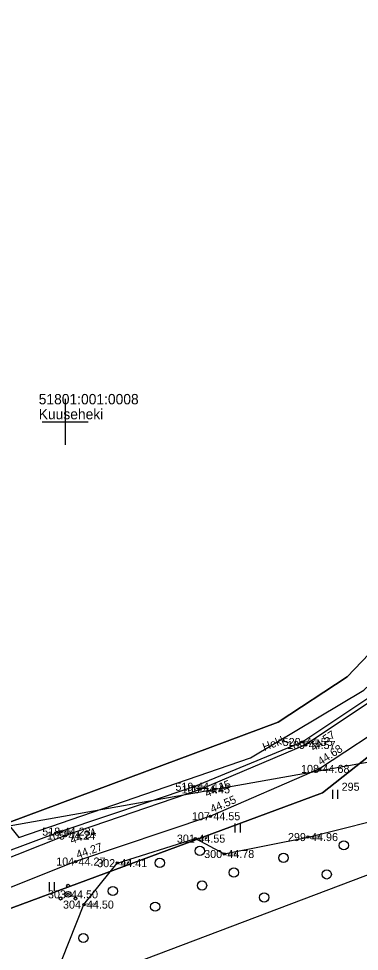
# Model space of a CAD drawing. Extents: x 505800 to 507326, y 6540058 to 6542128.
# Drawn here: x 506246 to 506275.6, y 6540254 to 6540335 of the extents above; entities that cross this region are included whole.
import ezdxf

# ---------------------------------------------------------------- set-up
doc = ezdxf.new("R2010")
doc.units = 0
for name, color, linetype in [('HALJASTUS', 7, 'Continuous'), ('KORGUS-EH2000', 7, 'Continuous'), ('MAAMUDEL', 7, 'Continuous'), ('MOOTKORG-EH2000', 7, 'Continuous'), ('MOOTMPUNKT', 7, 'Continuous'), ('MOOTNR', 7, 'Continuous'), ('MOOTPIIR', 7, 'Continuous'), ('MPOHULIIN', 7, 'Continuous'), ('PIIR', 7, 'Continuous'), ('PUU', 7, 'Continuous'), ('TEE', 7, 'Continuous'), ('VORK', 7, 'Continuous')]:
    doc.layers.add(name, color=color, linetype=linetype)

msp = doc.modelspace()

# ---------------------------------------------------------------- linework, layer by layer
at = {"layer": 'HALJASTUS'}
for p, q in [((506273.257, 6540268.004), (506273.257, 6540267.243)), ((506273.712, 6540268.004), (506273.712, 6540267.243)), ((506264.77, 6540265.08), (506264.77, 6540264.318)), ((506265.225, 6540265.08), (506265.225, 6540264.318)), ((506248.595, 6540259.992), (506248.595, 6540259.231)), ((506249.05, 6540259.992), (506249.05, 6540259.231))]:
    msp.add_line(p, q, dxfattribs=at)
for points in [[(506298.533, 6540313.056), (506300.788, 6540309.079), (506301.915, 6540305.332), (506301.34, 6540302.125), (506297.996, 6540298.309), (506290.085, 6540289.615), (506283.777, 6540282.658), (506277.199, 6540276.527), (506270.683, 6540272.177), (506261.206, 6540268.283), (506249.615, 6540264.383), (506241.896, 6540261.54), (506240.872, 6540264.129), (506242.157, 6540264.661)], [(506248.469, 6540250.071), (506251.633, 6540258.04), (506254.539, 6540261.644), (506261.335, 6540263.775), (506263.852, 6540262.439), (506271.144, 6540263.911), (506279.471, 6540265.984), (506282.803, 6540266.189), (506286.653, 6540264.508)]]:
    msp.add_lwpolyline(points, dxfattribs=at)
for centre in [(506261.718, 6540262.708), (506274.25, 6540263.188), (506269.005, 6540262.107), (506258.235, 6540261.666), (506264.681, 6540260.825), (506272.768, 6540260.664), (506261.918, 6540259.703), (506254.151, 6540259.222), (506267.323, 6540258.661), (506257.835, 6540257.86), (506251.589, 6540255.136)]:
    msp.add_circle(centre, 0.4, dxfattribs=at)
at = {"layer": 'KORGUS-EH2000'}
for centre in [(506270.683, 6540272.177), (506270.928, 6540271.917), (506272.138, 6540269.835), (506261.206, 6540268.283), (506261.747, 6540268.058), (506262.639, 6540265.724), (506249.615, 6540264.383), (506250.031, 6540264.042), (506261.335, 6540263.775), (506271.144, 6540263.911), (506263.852, 6540262.439), (506250.904, 6540261.782), (506254.539, 6540261.644), (506250.256, 6540258.933), (506251.633, 6540258.04)]:
    msp.add_circle(centre, 0.1, dxfattribs=at)
at = {"layer": 'MOOTMPUNKT'}
for centre in [(506270.683, 6540272.177), (506270.928, 6540271.917), (506272.138, 6540269.835), (506261.206, 6540268.283), (506261.747, 6540268.058), (506262.639, 6540265.724), (506249.615, 6540264.383), (506250.031, 6540264.042), (506261.335, 6540263.775), (506271.144, 6540263.911), (506263.852, 6540262.439), (506250.904, 6540261.782), (506254.539, 6540261.644), (506250.256, 6540258.933), (506251.633, 6540258.04)]:
    msp.add_circle(centre, 0.1, dxfattribs=at)
at = {"layer": 'MOOTPIIR'}
for points in [[(506240.253, 6540270.959), (506245.955, 6540263.864), (506266.133, 6540270.794), (506275.983, 6540276.683), (506285.511, 6540285.657), (506298.843, 6540299.878), (506301.086, 6540304.525), (506297.722, 6540312.738), (506305.023, 6540318.445), (506309.38, 6540311.746), (506312.325, 6540315.185), (506338.029, 6540330.648), (506336.908, 6540340.183), (506347.357, 6540347.554), (506370.89, 6540361.705), (506382.389, 6540366.462), (506390.076, 6540368.866), (506400.572, 6540374.13), (506410.565, 6540381.71), (506441.143, 6540393.151), (506453.59, 6540403.335), (506461.402, 6540393.473), (506495.448, 6540402.285)], [(506495.183, 6540386.603), (506455.807, 6540378.751), (506413.936, 6540356.957), (506411.426, 6540354.112), (506402.307, 6540351.523), (506391.999, 6540341.498), (506380.901, 6540334.942), (506360.247, 6540322.568), (506353.013, 6540324.95), (506332.133, 6540309.036), (506315.598, 6540297.889), (506301.375, 6540281.904), (506292.827, 6540267.673), (506286.653, 6540264.508), (506248.469, 6540250.071)]]:
    msp.add_lwpolyline(points, dxfattribs=at)
at = {"layer": 'MPOHULIIN'}
msp.add_lwpolyline([(506112.189, 6540233.927), (506153.828, 6540249.522), (506196.936, 6540256.778), (506240.207, 6540264.027), (506283.784, 6540271.755), (506305.802, 6540315.044)], dxfattribs=at)
at = {"layer": 'PIIR'}
for points in [[(506215.95, 6540254.34), (506268.55, 6540273.9), (506274.54, 6540277.85), (506304.35, 6540308.95), (506340.34, 6540335.82), (506458.7, 6540391.28), (506563.96, 6540420.02)], [(506497.85, 6540391.32), (506462.8, 6540384.69), (506453.27, 6540382.76), (506413.82, 6540364.84), (506374.55, 6540342.6), (506353.59, 6540332.53), (506318.07, 6540309.28), (506308, 6540301.95), (506281.65, 6540275.05), (506272.39, 6540267.75), (506224.13, 6540249.92)], [(506224.13, 6540249.92), (506272.39, 6540267.75), (506281.65, 6540275.05), (506308, 6540301.95), (506318.07, 6540309.28), (506353.59, 6540332.53), (506374.55, 6540342.6), (506413.82, 6540364.84), (506453.27, 6540382.76), (506462.8, 6540384.69), (506495.14, 6540337.45), (506342.85, 6540237.27), (506260.72, 6540195.9), (506215.68, 6540179.69)]]:
    msp.add_lwpolyline(points, dxfattribs=at)
msp.add_lwpolyline([(506190.15, 6540321.81), (506202.45, 6540325.81), (506206.43, 6540327.67), (506257.9, 6540343.01), (506275.56, 6540347.96), (506281.36, 6540349.61), (506282.62, 6540347.28), (506304.35, 6540308.95), (506274.54, 6540277.85), (506268.55, 6540273.9), (506215.95, 6540254.34)], close=True, dxfattribs=at)
at = {"layer": 'PUU'}
for centre, radius in [((506250.256, 6540259.683), 0.125), ((506250.256, 6540258.933), 0.25), ((506249.606, 6540258.558), 0.125), ((506250.906, 6540258.558), 0.125)]:
    msp.add_circle(centre, radius, dxfattribs=at)
at = {"layer": 'TEE'}
for points in [[(506340.898, 6540329.111), (506329.323, 6540321.237), (506318.831, 6540314.247), (506313.303, 6540310.828), (506310.542, 6540309.512), (506307.759, 6540307.29), (506302.957, 6540302.479), (506299.99, 6540299.616), (506292.541, 6540291.599), (506284.251, 6540282.595), (506277.243, 6540276.116), (506270.928, 6540271.917), (506261.747, 6540268.058), (506250.031, 6540264.042), (506237.432, 6540259.066)], [(506342.338, 6540327.065), (506330.786, 6540319.25), (506320.213, 6540312.197), (506313.574, 6540307.593), (506309.643, 6540304.666), (506301.827, 6540297.731), (506294.306, 6540290.01), (506285.858, 6540280.887), (506278.831, 6540274.243), (506272.138, 6540269.835), (506262.639, 6540265.724), (506250.904, 6540261.782), (506238.366, 6540256.809)]]:
    msp.add_lwpolyline(points, dxfattribs=at)
at = {"layer": 'VORK'}
for p, q in [((506250, 6540302), (506250, 6540298)), ((506248, 6540300), (506252, 6540300))]:
    msp.add_line(p, q, dxfattribs=at)

# ---------------------------------------------------------------- texts
at = {"layer": 'HALJASTUS'}
msp.add_text('Hekk', height=0.7, rotation=21.06856, dxfattribs=at).set_placement((506267.34, 6540271.376))
at = {"layer": 'KORGUS-EH2000'}
for s, rotation, p in [(' 44.57', 33.62657, (506271.413, 6540271.188)), (' 44.68', 33.36804, (506272.042, 6540269.982)), (' 44.45', 22.79749, (506262.086, 6540267.251)), (' 44.55', 23.40174, (506262.569, 6540265.885)), (' 44.24', 18.91832, (506250.314, 6540263.215)), (' 44.27', 18.56755, (506250.848, 6540261.948))]:
    msp.add_text(s, height=0.7, rotation=rotation, dxfattribs=at).set_placement(p)
for s, p in [(' 44.96', (506271.144, 6540263.561)), (' 44.78', (506263.852, 6540262.089)), (' 44.41', (506254.539, 6540261.294)), (' 44.50', (506251.633, 6540257.69))]:
    msp.add_text(s, height=0.7, dxfattribs=at).set_placement(p)
at = {"layer": 'MAAMUDEL'}
for s, p in [(' hek', (506270.683, 6540272.002)), (' hek', (506261.206, 6540268.108)), (' hek', (506249.615, 6540264.208)), (' mets', (506261.335, 6540263.6)), (' mets', (506271.144, 6540263.736)), (' mets', (506263.852, 6540262.264)), (' mets', (506254.539, 6540261.469)), (' mets', (506251.633, 6540257.865))]:
    msp.add_text(s, height=0.35, dxfattribs=at).set_placement(p)
at = {"layer": 'MOOTKORG-EH2000'}
for s, p in [(' 44.55', (506270.683, 6540271.827)), (' 44.57', (506270.928, 6540271.567)), (' 44.68', (506272.138, 6540269.485)), (' 44.41', (506261.206, 6540267.933)), (' 44.45', (506261.747, 6540267.708)), (' 44.55', (506262.639, 6540265.374)), (' 44.23', (506249.615, 6540264.033)), (' 44.24', (506250.031, 6540263.692)), (' 44.55', (506261.335, 6540263.425)), (' 44.96', (506271.144, 6540263.561)), (' 44.27', (506250.904, 6540261.432)), (' 44.78', (506263.852, 6540262.089)), (' 44.41', (506254.539, 6540261.294)), (' 44.50', (506250.256, 6540258.583)), (' 44.50', (506251.633, 6540257.69))]:
    msp.add_text(s, height=0.7, dxfattribs=at).set_placement(p)
at = {"layer": 'MOOTNR'}
for s, p in [('520 ', (506268.933, 6540271.827)), ('109 ', (506269.318, 6540271.567)), ('108 ', (506270.528, 6540269.485)), ('519 ', (506259.596, 6540267.933)), ('295 ', (506274.063, 6540267.936)), ('106 ', (506260.137, 6540267.708)), ('107 ', (506261.029, 6540265.374)), ('518 ', (506248.005, 6540264.033)), ('105 ', (506248.421, 6540263.692)), ('301 ', (506259.725, 6540263.425)), ('299 ', (506269.394, 6540263.561)), ('104 ', (506249.224, 6540261.432)), ('300 ', (506262.102, 6540262.089)), ('302 ', (506252.789, 6540261.294)), ('303 ', (506248.506, 6540258.583)), ('304 ', (506249.813, 6540257.69))]:
    msp.add_text(s, height=0.7, dxfattribs=at).set_placement(p)
at = {"layer": 'PIIR'}
for s, p in [('51801:001:0008', (506247.7, 6540301.525)), ('Kuuseheki', (506247.7, 6540300.225))]:
    msp.add_text(s, height=0.9, dxfattribs=at).set_placement(p)

doc.saveas('drawing.dxf')
